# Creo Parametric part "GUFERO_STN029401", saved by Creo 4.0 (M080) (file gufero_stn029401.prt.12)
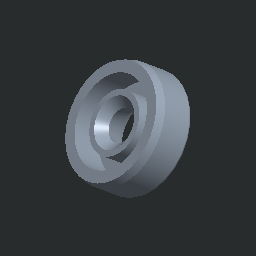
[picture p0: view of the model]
Units: Custom; MM, KILOGRAM, SECS
Materials in the file: POLYURETAN

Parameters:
  NAZOV = "GUFERO_STN029401"
  NORMA = "STN 02 9401"
  NAZOV_1 = "START_PART_IPM"
  PTC_MATERIAL_NAME = "POLYURETAN"
  PRO_UNIT_SYS = "IPM (mmkgsecC)"

Other parameters: HMOTNOST, HUSTOTA, HMOTNOST_1, HUSTOTA_1, D9, D2, D7, D5, D6, D0, D4, D1, D3, D8, D10, D12, D13

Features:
  1. round
  2. chamfer

Named dimensions: male_d, velke_D

Layers: 1, 2, 3, 4, 5, 6, 7, 8, 9, 10, 11, 12, 13, 14, 15, 16, 17, 18, 19, 20, 21, 22, 23, 24, 25, 26, 27, 28, 29, 30, 31, 32

Family table entries: GENERIC, GUFERO_6_16_7, GUFERO_STN029401, value(d_val), 2/0, value(i_val), GUFERO_6_22_7, GUFERO_STN029401, 2/6, GUFERO_7_22_7, GUFERO_STN029401, 2/6, GUFERO_8_16_7, GUFERO_STN029401, !/ , 2/0, GUFERO_8_22_7, GUFERO_STN029401, !/ , 2/6, GUFERO_8_24_7, GUFERO_STN029401, !/ , 2/8, GUFERO_9_22_7, GUFERO_STN029401, !/", 2/6, GUFERO_9_24_7, GUFERO_STN029401, !/", 2/8, GUFERO_9_26_7, GUFERO_STN029401, !/", 2/:, GUFERO_10_19_7, GUFERO_STN029401, !/$, 2/6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

Surfaces: 8 cone, 6 cylinder, 5 plane, 2 torus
